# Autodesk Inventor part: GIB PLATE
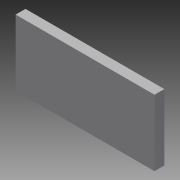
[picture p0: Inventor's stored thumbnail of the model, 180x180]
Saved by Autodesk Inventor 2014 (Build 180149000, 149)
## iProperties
Shininess: 64.0
Length Units: 11272
Angle Units: 11279
Time Units: 11290
Mass Units: 11286
Length Display Precision: 3
Angle Display Precision: 2
Compacted: True
Part Number: GIB PLATE
Document SubType Name: Modeling
Created: 2003-11
Designer: Autodesk, Inc.
Manufacturer: Standard
Standards Organization: Custom
Mass: 9.82621 g
Surface Area: 12.9097 cm^2
Volume: 1.25015 cm^3
Density: 7.86 g/cm^3
Material: Steel, Mild
Appearance: Steel
Density: 0.0
Volumn: 0.0
Area: 0.0
PropertySet Name: Model Information
Control State: 0
Master: False
Checked Out: False
Author: Autodesk, Inc.
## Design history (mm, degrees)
sketch "Sketch1"
  geometry: L1 (0, 0)-(33.338, 0); L2 (33.338, 0)-(33.338, 15.875); L3 (33.338, 15.875)-(0, 15.875); L4 (0, 15.875)-(0, 0)
  constraints: 8 end point, 2 parallel, 1 horizontal, 1 perpendicular
  dimensions: "d0" = 33.3375 distance of L1.start L1.end; "d1" = 15.875 distance between parallel lines of L1 L3
extrude "Extrusion1" new body sketch "Sketch1" distance "d2" = 2.3622; taper "d3" = 0 deg
body "Solid1"
